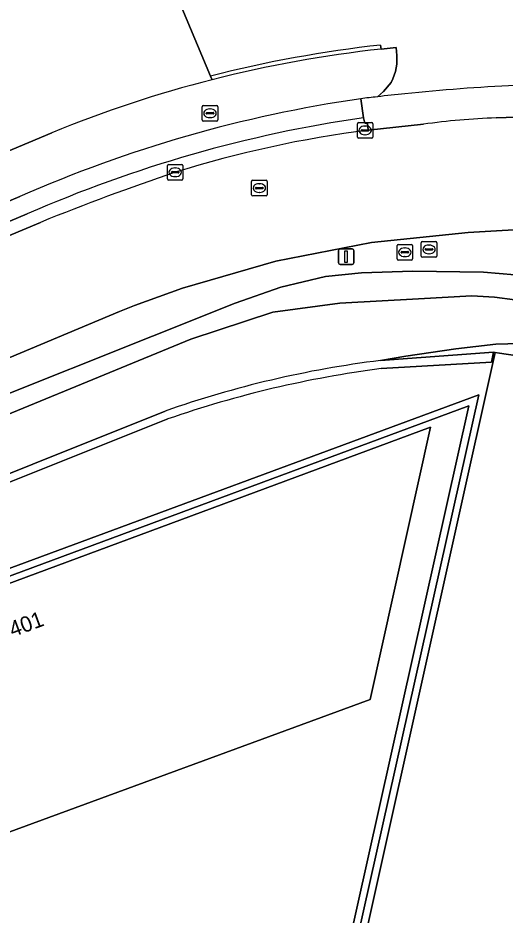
# Model space of a CAD drawing. Extents: x 161385 to 162589, y 388479 to 389756.
# Drawn here: x 162091.3 to 162122.7, y 388775.8 to 388833.4 of the extents above; entities that cross this region are included whole.
import ezdxf

# ---------------------------------------------------------------- set-up
doc = ezdxf.new("R2010")
doc.units = 0
for name, color, linetype in [('IMGEO_Berm_groen', 7, 'Continuous'), ('IMGEO_Erf', 7, 'Continuous'), ('IMGEO_Groenvoorziening', 7, 'Continuous'), ('IMGEO_Kolk', 7, 'Continuous'), ('IMGEO_Lichtmast', 7, 'Continuous'), ('IMGEO_Muur', 7, 'Continuous'), ('IMGEO_Oever', 7, 'Continuous'), ('IMGEO_Pand', 7, 'Continuous'), ('IMGEO_Pand_nummerreeks', 7, 'Continuous'), ('IMGEO_Rijbaan_lokaal_gesloten', 7, 'Continuous'), ('IMGEO_Rioolput', 7, 'Continuous'), ('IMGEO_Voetpad_open', 7, 'Continuous'), ('IMGEO_Waterloop', 7, 'Continuous')]:
    doc.layers.add(name, color=color, linetype=linetype)

msp = doc.modelspace()

# ---------------------------------------------------------------- linework, layer by layer
at = {"layer": 'IMGEO_Berm_groen'}
for points in [[(162113.856, 388826.23), (162113.818, 388826.674), (162113.633, 388826.682), (162113.555, 388827.022)], [(162091.936, 388820.838), (162051.101, 388803.612), (162049.152, 388802.833)], [(162050.467, 388802.522), (162066.195, 388809.127), (162083.964, 388816.605), (162092.793, 388820.3)]]:
    msp.add_lwpolyline(points, dxfattribs=at)
for centre, radius, start, end in [((162125.536, 388744.255), 83.63, 98.23677, 113.68902), ((162123.328, 388753.174), 73.667, 97.38714, 107.28112), ((162151.527, 388675.55), 156.212, 108.69972, 112.08541)]:
    msp.add_arc(centre, radius, start, end, dxfattribs=at)
at = {"layer": 'IMGEO_Erf'}
for points in [[(162081.552, 388882.482), (162096.812, 388887.735), (162107.787, 388861.603), (162092.944, 388855.366), (162094.499, 388851.664), (162103.725, 388829.704)], [(162114.658, 388831.69), (162114.685, 388831.432), (162115.65, 388831.534), (162115.698, 388831.024), (162115.698, 388830.464), (162115.622, 388830.003), (162115.447, 388829.518), (162115.323, 388829.293), (162114.833, 388828.711), (162114.449, 388828.37)], [(162089.771, 388797.682), (162120.964, 388809.223), (162106.946, 388746.548), (162107.264, 388745.692), (162122.012, 388811.944), (162121.91, 388811.96), (162121.786, 388811.312), (162114.695, 388810.898)], [(162091.135, 388774.03), (162093.235, 388768.019), (162098.238, 388769.844), (162098.752, 388768.604), (162105.908, 388749.278), (162106.664, 388747.307), (162120.333, 388808.51), (162090.394, 388797.404)], [(162100.979, 388807.667), (162082.944, 388800.482)], [(162090.544, 388797), (162117.872, 388807.131), (162113.978, 388789.645), (162090.149, 388780.9)]]:
    msp.add_lwpolyline(points, dxfattribs=at)
for centre, radius, start, end in [((162123.315, 388752.947), 79.218, 96.27386, 104.31738), ((162129.621, 388698.352), 130.9, 92.75442, 95.87794), ((162128.182, 388711.433), 117.741, 95.83292, 96.69797), ((162123.469, 388742.924), 68.538, 97.35473, 109.15565)]:
    msp.add_arc(centre, radius, start, end, dxfattribs=at)
at = {"layer": 'IMGEO_Groenvoorziening'}
for points in [[(162114.449, 388828.37), (162114.833, 388828.711), (162115.323, 388829.293), (162115.447, 388829.518), (162115.622, 388830.003), (162115.698, 388830.464), (162115.698, 388831.024), (162115.65, 388831.534), (162114.685, 388831.432)], [(162093.508, 388826.06), (162048.347, 388807.09), (162045.228, 388813.835), (162038.345, 388810.652), (162035.583, 388816.547)], [(162048.684, 388803.926), (162050.304, 388804.628), (162091.45, 388821.953)], [(162195.671, 388802.792), (162140.186, 388818.105), (162139.775, 388818.192), (162138.364, 388818.491), (162135.196, 388819.162), (162130.132, 388819.769), (162125.034, 388819.921), (162120.283, 388819.652), (162114.064, 388819.011), (162107.927, 388817.816), (162101.922, 388816.079), (162098.832, 388814.951), (162097.873, 388814.565), (162080.428, 388807.257)], [(162084.128, 388806.673), (162105.294, 388815.098), (162108.229, 388816.145), (162111.109, 388816.824), (162113.431, 388817.054), (162116.728, 388817.154), (162121.274, 388817.091), (162123.279, 388816.923), (162124.621, 388816.592), (162125.847, 388816.04), (162126.653, 388815.521), (162127.227, 388814.805), (162127.402, 388813.932), (162127.324, 388813.04), (162126.889, 388812.087), (162126.404, 388811.638), (162125.709, 388811.263), (162125.257, 388811.171), (162124.523, 388811.269), (162123.296, 388811.736), (162122.289, 388811.888), (162122.012, 388811.944), (162107.264, 388745.692)]]:
    msp.add_lwpolyline(points, dxfattribs=at)
for centre, radius, start, end in [((162123.226, 388753.364), 78.534, 96.24331, 104.30138), ((162123.291, 388753.124), 78.783, 104.3042, 112.21217), ((162125.465, 388744.723), 84.389, 98.2379, 113.77021), ((162125.644, 388730.438), 98.57, 96.52151, 97.15144)]:
    msp.add_arc(centre, radius, start, end, dxfattribs=at)
at = {"layer": 'IMGEO_Kolk'}
for p, q in [((162113.158, 388825.783), (162113.158, 388826.635)), ((162113.233, 388826.709), (162114.085, 388826.709)), ((162113.646, 388826.489), (162113.671, 388826.489)), ((162114.159, 388826.635), (162114.159, 388825.783)), ((162113.417, 388826.203), (162113.417, 388826.215)), ((162113.855, 388826.166), (162113.457, 388826.166)), ((162113.46, 388826.252), (162113.858, 388826.252)), ((162113.669, 388825.929), (162113.644, 388825.929)), ((162113.901, 388826.215), (162113.901, 388826.203)), ((162114.085, 388825.709), (162113.233, 388825.709)), ((162101.018, 388824.017), (162101.87, 388824.017)), ((162100.943, 388823.091), (162100.943, 388823.943)), ((162101.202, 388823.511), (162101.202, 388823.523)), ((162101.64, 388823.474), (162101.242, 388823.474)), ((162101.245, 388823.56), (162101.643, 388823.56)), ((162101.431, 388823.797), (162101.456, 388823.797)), ((162101.686, 388823.523), (162101.686, 388823.511)), ((162101.944, 388823.943), (162101.944, 388823.091)), ((162101.87, 388823.017), (162101.018, 388823.017)), ((162101.454, 388823.237), (162101.429, 388823.237))]:
    msp.add_line(p, q, dxfattribs=at)
for points in [[(162113.158, 388825.783), (162113.158, 388826.635)], [(162113.233, 388826.709), (162114.085, 388826.709)], [(162114.159, 388826.635), (162114.159, 388825.783)], [(162114.085, 388825.709), (162113.233, 388825.709)], [(162101.018, 388824.017), (162101.87, 388824.017)], [(162100.943, 388823.091), (162100.943, 388823.943)], [(162101.944, 388823.943), (162101.944, 388823.091)], [(162101.87, 388823.017), (162101.018, 388823.017)]]:
    msp.add_lwpolyline(points, dxfattribs=at)
for centre, radius, start, end in [((162113.235, 388826.633), 0.0765, 91.55205, 178.44795), ((162113.235, 388826.633), 0.0765, 91.55205, 178.44795), ((162114.083, 388826.633), 0.0765, 1.55205, 88.44795), ((162114.083, 388826.633), 0.0765, 1.55205, 88.44795), ((162113.235, 388825.785), 0.0765, 181.55205, 268.44795), ((162113.235, 388825.785), 0.0765, 181.55205, 268.44795), ((162113.457, 388826.212), 0.0403, 85.87752, 175.75265), ((162113.454, 388826.202), 0.0366, 178.93798, 274.71019), ((162113.858, 388826.209), 0.043, 264.86636, 352.45326), ((162113.862, 388826.214), 0.0386, 1.73085, 96.63898), ((162114.083, 388825.785), 0.0765, 271.55205, 358.44795), ((162114.083, 388825.785), 0.0765, 271.55205, 358.44795), ((162101.02, 388823.941), 0.0765, 91.55205, 178.44795), ((162101.02, 388823.941), 0.0765, 91.55205, 178.44795), ((162101.868, 388823.941), 0.0765, 1.55205, 88.44795), ((162101.868, 388823.941), 0.0765, 1.55205, 88.44795), ((162101.242, 388823.52), 0.0403, 85.87752, 175.75265), ((162101.239, 388823.51), 0.0366, 178.93798, 274.71019), ((162101.643, 388823.517), 0.043, 264.86636, 352.45326), ((162101.647, 388823.522), 0.0386, 1.73085, 96.63898), ((162101.02, 388823.093), 0.0765, 181.55205, 268.44795), ((162101.02, 388823.093), 0.0765, 181.55205, 268.44795), ((162101.868, 388823.093), 0.0765, 271.55205, 358.44795), ((162101.868, 388823.093), 0.0765, 271.55205, 358.44795)]:
    msp.add_arc(centre, radius, start, end, dxfattribs=at)
for centre, major_axis, ratio, start_param, end_param in [((162113.645, 388826.209), (-0.387, 0.002), 0.722429, 4.712389, 7.853982), ((162113.67, 388826.209), (-0.39, 0.002), 0.717154, 1.570796, 4.712389), ((162101.43, 388823.517), (-0.387, 0.002), 0.722429, 4.712389, 7.853982), ((162101.455, 388823.517), (-0.39, 0.002), 0.717154, 1.570796, 4.712389)]:
    msp.add_ellipse(centre, major_axis=major_axis, ratio=ratio, start_param=start_param, end_param=end_param, dxfattribs=at)
at = {"layer": 'IMGEO_Lichtmast'}
for p, q in [((162111.944, 388817.695), (162111.944, 388818.495)), ((162111.944, 388818.495), (162111.944, 388817.695)), ((162112.044, 388818.595), (162112.834, 388818.595)), ((162112.834, 388818.595), (162112.044, 388818.595)), ((162112.934, 388818.495), (162112.934, 388817.695)), ((162112.934, 388817.695), (162112.934, 388818.495)), ((162112.834, 388817.595), (162112.044, 388817.595)), ((162112.044, 388817.595), (162112.834, 388817.595))]:
    msp.add_line(p, q, dxfattribs=at)
msp.add_lwpolyline([(162112.364, 388818.47), (162112.514, 388818.47), (162112.514, 388817.72), (162112.364, 388817.72), (162112.364, 388818.47)], dxfattribs=at)
for centre, start, end in [((162112.044, 388818.495), 90, 180), ((162112.044, 388818.495), 90, 180), ((162112.834, 388818.495), 0, 90), ((162112.834, 388818.495), 360, 90), ((162112.044, 388817.695), 180, 270), ((162112.044, 388817.695), 180, 270), ((162112.834, 388817.695), 270, 0), ((162112.834, 388817.695), 270, 0)]:
    msp.add_arc(centre, 0.1, start, end, dxfattribs=at)
at = {"layer": 'IMGEO_Muur'}
for points in [[(162114.685, 388831.432), (162114.658, 388831.69)], [(162103.725, 388829.704), (162103.826, 388829.464)], [(162114.695, 388810.898), (162121.786, 388811.312), (162121.91, 388811.96), (162114.641, 388811.421)], [(162100.792, 388808.167), (162083.759, 388801.362), (162083.699, 388801.518), (162082.695, 388801.152), (162082.944, 388800.482), (162100.979, 388807.667)]]:
    msp.add_lwpolyline(points, dxfattribs=at)
msp.add_lwpolyline([(162105.447, 388749.108), (162106.601, 388746.014), (162058.944, 388728.375), (162053.195, 388743.617), (162052.765, 388743.449), (162058.659, 388727.729), (162106.287, 388745.331), (162107.264, 388745.692), (162106.946, 388746.548), (162120.964, 388809.223), (162089.771, 388797.682), (162090.089, 388796.832), (162090.544, 388797), (162090.394, 388797.404), (162120.333, 388808.51), (162106.664, 388747.307), (162105.908, 388749.278)], close=True, dxfattribs=at)
for centre, radius, start, end in [((162123.315, 388752.947), 79.218, 96.27386, 104.31738), ((162123.226, 388753.364), 78.534, 96.24331, 104.30138), ((162122.776, 388745.701), 66.222, 97.05634, 109.38872), ((162123.469, 388742.924), 68.538, 97.35473, 109.15565)]:
    msp.add_arc(centre, radius, start, end, dxfattribs=at)
at = {"layer": 'IMGEO_Oever'}
for points in [[(162123.279, 388816.923), (162121.274, 388817.091), (162116.728, 388817.154), (162113.431, 388817.054), (162111.109, 388816.824), (162108.229, 388816.145), (162105.294, 388815.098), (162084.128, 388806.673)], [(162085.348, 388805.764), (162102.46, 388812.799), (162107.717, 388814.524), (162112.029, 388815.099), (162117.08, 388815.386), (162120.525, 388815.567), (162121.984, 388815.497), (162123.275, 388815.323)], [(162123.597, 388812.518), (162122.054, 388812.471), (162119.499, 388812.17), (162116.283, 388811.708), (162114.641, 388811.421), (162121.91, 388811.96), (162122.012, 388811.944), (162122.289, 388811.888), (162123.296, 388811.736)]]:
    msp.add_lwpolyline(points, dxfattribs=at)
at = {"layer": 'IMGEO_Pand'}
for points in [[(162103.826, 388829.464), (162103.725, 388829.704), (162094.499, 388851.664), (162092.944, 388855.366), (162107.787, 388861.603), (162096.812, 388887.735), (162081.552, 388882.482)], [(162048.347, 388807.09), (162093.508, 388826.06)]]:
    msp.add_lwpolyline(points, dxfattribs=at)
msp.add_lwpolyline([(162090.149, 388780.9), (162113.978, 388789.645), (162117.872, 388807.131), (162090.544, 388797), (162090.089, 388796.832), (162084.904, 388794.91)], close=True, dxfattribs=at)
msp.add_arc((162123.291, 388753.124), 78.783, 104.3042, 112.21217, dxfattribs=at)
at = {"layer": 'IMGEO_Rijbaan_lokaal_gesloten'}
for points in [[(162125.996, 388827.14), (162122.089, 388827.012)], [(162117.407, 388826.602), (162113.856, 388826.23)], [(162092.793, 388820.3), (162083.964, 388816.605), (162066.195, 388809.127), (162050.467, 388802.522)], [(162080.428, 388807.257), (162097.873, 388814.565), (162098.832, 388814.951), (162101.922, 388816.079), (162107.927, 388817.816), (162114.064, 388819.011), (162120.283, 388819.652), (162125.034, 388819.921), (162130.132, 388819.769), (162135.196, 388819.162), (162138.364, 388818.491), (162139.775, 388818.192), (162140.186, 388818.105), (162195.671, 388802.792), (162202.77, 388800.823), (162211.048, 388798.507)]]:
    msp.add_lwpolyline(points, dxfattribs=at)
for centre, radius, start, end in [((162123.435, 388784.701), 42.333, 91.82236, 98.18682), ((162123.328, 388753.174), 73.667, 97.38714, 107.28112), ((162151.527, 388675.55), 156.212, 108.69972, 112.08541)]:
    msp.add_arc(centre, radius, start, end, dxfattribs=at)
at = {"layer": 'IMGEO_Rioolput'}
for p, q in [((162103.184, 388826.881), (162103.184, 388827.733)), ((162103.259, 388827.807), (162104.111, 388827.807)), ((162103.672, 388827.587), (162103.697, 388827.587)), ((162104.185, 388827.733), (162104.185, 388826.881)), ((162103.443, 388827.301), (162103.443, 388827.313)), ((162103.881, 388827.264), (162103.483, 388827.264)), ((162103.486, 388827.35), (162103.884, 388827.35)), ((162103.695, 388827.027), (162103.67, 388827.027)), ((162103.927, 388827.313), (162103.927, 388827.301)), ((162104.111, 388826.807), (162103.259, 388826.807)), ((162106.358, 388822.077), (162106.358, 388822.929)), ((162106.433, 388823.003), (162107.285, 388823.003)), ((162107.359, 388822.929), (162107.359, 388822.077)), ((162106.617, 388822.497), (162106.617, 388822.509)), ((162107.055, 388822.46), (162106.657, 388822.46)), ((162106.66, 388822.546), (162107.058, 388822.546)), ((162106.846, 388822.783), (162106.871, 388822.783)), ((162107.101, 388822.509), (162107.101, 388822.497)), ((162107.285, 388822.003), (162106.433, 388822.003)), ((162106.869, 388822.223), (162106.844, 388822.223)), ((162115.785, 388818.877), (162116.637, 388818.877)), ((162117.271, 388818.134), (162117.271, 388818.986)), ((162117.346, 388819.06), (162118.198, 388819.06)), ((162117.759, 388818.84), (162117.784, 388818.84)), ((162118.272, 388818.986), (162118.272, 388818.134)), ((162115.71, 388817.951), (162115.71, 388818.803)), ((162115.969, 388818.371), (162115.969, 388818.383)), ((162116.407, 388818.334), (162116.009, 388818.334)), ((162116.012, 388818.42), (162116.41, 388818.42)), ((162116.198, 388818.657), (162116.223, 388818.657)), ((162116.453, 388818.383), (162116.453, 388818.371)), ((162116.711, 388818.803), (162116.711, 388817.951)), ((162117.53, 388818.554), (162117.53, 388818.566)), ((162117.968, 388818.517), (162117.57, 388818.517)), ((162117.573, 388818.603), (162117.971, 388818.603)), ((162117.782, 388818.28), (162117.757, 388818.28)), ((162118.014, 388818.566), (162118.014, 388818.554)), ((162116.637, 388817.877), (162115.785, 388817.877)), ((162116.221, 388818.097), (162116.196, 388818.097)), ((162118.198, 388818.06), (162117.346, 388818.06))]:
    msp.add_line(p, q, dxfattribs=at)
for points in [[(162103.184, 388826.881), (162103.184, 388827.733)], [(162103.259, 388827.807), (162104.111, 388827.807)], [(162104.185, 388827.733), (162104.185, 388826.881)], [(162104.111, 388826.807), (162103.259, 388826.807)], [(162106.358, 388822.077), (162106.358, 388822.929)], [(162106.433, 388823.003), (162107.285, 388823.003)], [(162107.359, 388822.929), (162107.359, 388822.077)], [(162107.285, 388822.003), (162106.433, 388822.003)], [(162115.785, 388818.877), (162116.637, 388818.877)], [(162117.271, 388818.134), (162117.271, 388818.986)], [(162117.346, 388819.06), (162118.198, 388819.06)], [(162118.272, 388818.986), (162118.272, 388818.134)], [(162115.71, 388817.951), (162115.71, 388818.803)], [(162116.711, 388818.803), (162116.711, 388817.951)], [(162116.637, 388817.877), (162115.785, 388817.877)], [(162118.198, 388818.06), (162117.346, 388818.06)]]:
    msp.add_lwpolyline(points, dxfattribs=at)
for centre, radius, start, end in [((162103.261, 388827.731), 0.0765, 91.55205, 178.44795), ((162103.261, 388827.731), 0.0765, 91.55205, 178.44795), ((162104.109, 388827.731), 0.0765, 1.55205, 88.44795), ((162104.109, 388827.731), 0.0765, 1.55205, 88.44795), ((162103.261, 388826.883), 0.0765, 181.55205, 268.44795), ((162103.261, 388826.883), 0.0765, 181.55205, 268.44795), ((162103.483, 388827.31), 0.0403, 85.87752, 175.75265), ((162103.48, 388827.3), 0.0366, 178.93798, 274.71019), ((162103.884, 388827.307), 0.043, 264.86636, 352.45326), ((162103.888, 388827.312), 0.0386, 1.73085, 96.63898), ((162104.109, 388826.883), 0.0765, 271.55205, 358.44795), ((162104.109, 388826.883), 0.0765, 271.55205, 358.44795), ((162106.435, 388822.927), 0.0765, 91.55205, 178.44795), ((162106.435, 388822.927), 0.0765, 91.55205, 178.44795), ((162107.283, 388822.927), 0.0765, 1.55205, 88.44795), ((162107.283, 388822.927), 0.0765, 1.55205, 88.44795), ((162106.657, 388822.506), 0.0403, 85.87752, 175.75265), ((162106.654, 388822.496), 0.0366, 178.93798, 274.71019), ((162107.058, 388822.503), 0.043, 264.86636, 352.45326), ((162107.062, 388822.508), 0.0386, 1.73085, 96.63898), ((162106.435, 388822.079), 0.0765, 181.55205, 268.44795), ((162106.435, 388822.079), 0.0765, 181.55205, 268.44795), ((162107.283, 388822.079), 0.0765, 271.55205, 358.44795), ((162107.283, 388822.079), 0.0765, 271.55205, 358.44795), ((162115.787, 388818.801), 0.0765, 91.55205, 178.44795), ((162115.787, 388818.801), 0.0765, 91.55205, 178.44795), ((162116.635, 388818.801), 0.0765, 1.55205, 88.44795), ((162116.635, 388818.801), 0.0765, 1.55205, 88.44795), ((162117.348, 388818.984), 0.0765, 91.55205, 178.44795), ((162117.348, 388818.984), 0.0765, 91.55205, 178.44795), ((162118.196, 388818.984), 0.0765, 1.55205, 88.44795), ((162118.196, 388818.984), 0.0765, 1.55205, 88.44795), ((162116.009, 388818.38), 0.0403, 85.87752, 175.75265), ((162116.006, 388818.37), 0.0366, 178.93798, 274.71019), ((162116.41, 388818.377), 0.043, 264.86636, 352.45326), ((162116.414, 388818.382), 0.0386, 1.73085, 96.63898), ((162117.57, 388818.563), 0.0403, 85.87752, 175.75265), ((162117.567, 388818.553), 0.0366, 178.93798, 274.71019), ((162117.971, 388818.56), 0.043, 264.86636, 352.45326), ((162117.975, 388818.565), 0.0386, 1.73085, 96.63898), ((162115.787, 388817.953), 0.0765, 181.55205, 268.44795), ((162115.787, 388817.953), 0.0765, 181.55205, 268.44795), ((162116.635, 388817.953), 0.0765, 271.55205, 358.44795), ((162116.635, 388817.953), 0.0765, 271.55205, 358.44795), ((162117.348, 388818.136), 0.0765, 181.55205, 268.44795), ((162117.348, 388818.136), 0.0765, 181.55205, 268.44795), ((162118.196, 388818.136), 0.0765, 271.55205, 358.44795), ((162118.196, 388818.136), 0.0765, 271.55205, 358.44795)]:
    msp.add_arc(centre, radius, start, end, dxfattribs=at)
for centre, major_axis, ratio, start_param, end_param in [((162103.671, 388827.307), (-0.387, 0.002), 0.722429, 4.712389, 7.853982), ((162103.696, 388827.307), (-0.39, 0.002), 0.717154, 1.570796, 4.712389), ((162106.845, 388822.503), (-0.387, 0.002), 0.722429, 4.712389, 7.853982), ((162106.87, 388822.503), (-0.39, 0.002), 0.717154, 1.570796, 4.712389), ((162117.758, 388818.56), (-0.387, 0.002), 0.722429, 4.712389, 7.853982), ((162117.783, 388818.56), (-0.39, 0.002), 0.717154, 1.570796, 4.712389), ((162116.197, 388818.377), (-0.387, 0.002), 0.722429, 4.712389, 7.853982), ((162116.222, 388818.377), (-0.39, 0.002), 0.717154, 1.570796, 4.712389)]:
    msp.add_ellipse(centre, major_axis=major_axis, ratio=ratio, start_param=start_param, end_param=end_param, dxfattribs=at)
at = {"layer": 'IMGEO_Voetpad_open'}
for points in [[(162113.373, 388828.241), (162113.555, 388827.022), (162113.633, 388826.682), (162113.818, 388826.674), (162113.856, 388826.23), (162117.407, 388826.602)], [(162113.555, 388827.022), (162113.373, 388828.241)], [(162122.089, 388827.012), (162125.996, 388827.14), (162125.977, 388828.06)], [(162091.45, 388821.953), (162050.304, 388804.628), (162048.684, 388803.926), (162049.152, 388802.833), (162051.101, 388803.612), (162091.936, 388820.838)]]:
    msp.add_lwpolyline(points, dxfattribs=at)
for centre, radius, start, end in [((162129.621, 388698.352), 130.9, 92.75442, 95.87794), ((162125.465, 388744.723), 84.389, 98.2379, 113.77021), ((162125.644, 388730.438), 98.57, 96.52151, 97.15144), ((162128.182, 388711.433), 117.741, 95.83292, 96.69797), ((162125.536, 388744.255), 83.63, 98.23677, 113.68902), ((162123.435, 388784.701), 42.333, 91.82236, 98.18682)]:
    msp.add_arc(centre, radius, start, end, dxfattribs=at)
at = {"layer": 'IMGEO_Waterloop'}
for points in [[(162114.641, 388811.421), (162116.283, 388811.708), (162119.499, 388812.17), (162122.054, 388812.471), (162123.597, 388812.518), (162125.076, 388812.206), (162125.8, 388812.119), (162126.158, 388812.191), (162126.307, 388812.599), (162126.341, 388813.124), (162126.007, 388813.693), (162125.548, 388814.314), (162125.004, 388814.748), (162124.313, 388815.034), (162123.275, 388815.323), (162121.984, 388815.497), (162120.525, 388815.567), (162117.08, 388815.386), (162112.029, 388815.099), (162107.717, 388814.524), (162102.46, 388812.799), (162085.348, 388805.764)], [(162083.759, 388801.362), (162100.792, 388808.167)]]:
    msp.add_lwpolyline(points, dxfattribs=at)
msp.add_arc((162122.776, 388745.701), 66.222, 97.05634, 109.38872, dxfattribs=at)

# ---------------------------------------------------------------- texts
at = {"layer": 'IMGEO_Pand_nummerreeks'}
msp.add_text('401', height=1, rotation=20.29757, dxfattribs=at).set_placement((162090.994, 388793.633))

doc.saveas('drawing.dxf')
